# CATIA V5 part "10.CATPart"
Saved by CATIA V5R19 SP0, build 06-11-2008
Part number: 10
Bounding box of the stored display mesh (mm): x -125 to 125, y -74.978 to 485, z -260.425 to 324.922
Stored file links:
  G:\EU_thinkMotion\CFAO_2010\MMS_groupe3\MMS_groupe3\A reprendre\bblot\BLOT\10.CATPart
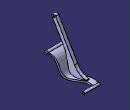
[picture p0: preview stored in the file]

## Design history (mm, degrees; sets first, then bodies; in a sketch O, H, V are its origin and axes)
Body1 (main body)
  DatumCurve1
  DatumCurve2
  Plane1 "Plan 9-10 droite": stored without definition
  Plane2 "Plan 9-10 gauche": stored without definition
  DatumSurface1
  Sketch1 on xy-plane, origin (0, 0, 0), H (1, 0, 0), V (0, 1, 0)
    point P1 (-125, 0)
    line L1 (-125, 0) -> (-125, 12.5)
    line L2 (-125, 12.5) -> (-100, 12.5)
    line L3 (-100, 12.5) -> (-100, 17)
    line L4 (-100, 17) -> (100, 17)
    line L5 (100, 17) -> (100, 12.5)
    point P6 (100, 12.5)
    line L6 (100, 12.5) -> (125, 12.5)
    line L7 (125, 12.5) -> (125, 0)
    point P8 (125, 0)
    line L8 (125, 0) -> (-125, 0)
    reference projected line E1 (-120, 40) -> (-120, -40) from edge of DatumCurve1
    reference projected line E2 (120, 40) -> (120, -160) from edge of DatumCurve2
    reference intersected line E3 through (-100, 0) direction (0, 1) from Plane1
    reference intersected line E4 through (100, 0) direction (0, 1) from Plane2
    axis line L9 (125, 0) -> (-125, 0)
    distance E1 L1 = 5
    distance L7 E2 = 5
    distance L2 L8 = 12.5
    distance L8 L4 = 17
    coincidence: P1 H, P6 L2, P8 H, L3 E3, L5 E4
    vertical: L1 V, L3 V, L5 V, L7 V
    horizontal: L2 H, L4 H, L6 H, L8 H, L9 H
  Shaft1: profile Sketch1, axis Sketch1.L9, angle 360
  DatumCurve3
  DatumSurface2
  Sketch2 on face of DatumSurface1, origin (-100, 0, 0), H (0, -1, 0), V (0, 0, 1)
    circle A1 centre (-470, -220) radius 10
    circle A2 centre (-470, -220) radius 15
    reference projected circle E1 centre (-470, -220) radius 10 from edge of DatumCurve3
    distance A1 A2 = 5
    coincidence: A1 E1
  Pad1: profile Sketch2, direction (-1, 0, 0), up to face of DatumSurface2
  Line1 "BE": stored without definition
  Line2 "as (BF)": stored without definition
  Plane3: type 2Lines, Element1 Line1, Element2 Line2
  Line3 "ab": stored without definition
  Plane4 "Plan 9-10 gauche": stored without definition
  Line4 "as (BF)": stored without definition
  DatumSurface3
  DatumSurface4
  Line5 "ab": stored without definition
  Plane5 "Plan 9-10 droite": stored without definition
  Plane6 "Fig.2": stored without definition
  Plane7 "Fig.2": stored without definition
  Sketch3 on Plane6, origin (0, 0, 0), H (0, 1, 0), V (0, 0, 1)
    construction line L1 (12.2365, 2.5533) -> (5.8774, -11.0321)
    point P1 (12.2365, 2.5533)
    point P2 (5.8774, -11.0321)
    reference projected point E1 (9.0569, -4.2394) from vertex [element of Sketch4 | element of Sketch4]
    reference projected circle E2 centre (0, 0) radius 12.5 from edge [face of Shaft1 from Sketch1.L7 | face of Shaft1 from Sketch1.L6]
    reference projected circle E3 centre (0, 0) radius 12.5 from edge [face of Shaft1 from Sketch1.L7 | face of Shaft1 from Sketch1.L6]
    arc A1 centre (0, 0) radius 12.5 from (5.8774, -11.0321) to (12.2365, 2.5533) ccw
    axis line L2 (462.9472, -206.7615) -> (455.3163, -223.0639)
    point P4 (462.9472, -206.7615)
    point P5 (455.3163, -223.0639)
    reference projected point E4 (459.1317, -214.9127) from vertex [element of Sketch4 | element of Sketch4]
    reference projected circle E5 centre (470, -220) radius 15 from edge [face of Pad1 from Sketch2.A2 | end face of Pad1]
    reference projected circle E6 centre (470, -220) radius 15 from edge [face of Pad1 from Sketch2.A2 | end face of Pad1]
    arc A2 centre (470, -220) radius 15 from (462.9472, -206.7615) to (455.3163, -223.0639) ccw
    point P7 (462.9472, -206.7615)
    reference projected circle E7 centre (470, -220) radius 15 from edge [face of Pad1 from Sketch2.A2 | end face of Pad1]
    spline S1 through (455.3163, -223.0639) (350, -230) (140, -240) (75, -45) (5.8774, -11.0321)
    spline S2 through (462.9472, -206.7615) (340, -210) (160, -220) (100, -43) (12.2365, 2.5533)
    reference projected line E8 through (0, 0) direction (1, 0) from Line11
    reference projected line E9 through (0, 0) direction (0, 1) from Line12
    reference projected line E10 through (0, 0) direction (0, 1) from Line13
    reference projected line E11 (0, 0) -> (470, 0) from Line14
    reference projected line E12 through (0, 0) direction (0, 1) from Line15
    reference projected line E13 through (0, 0) direction (1, 0) from Line16
    reference projected line E14 through (0, 0) direction (1, 0) from Line17
    reference projected line E15 through (0, 0) direction (0, 1) from Line18
    reference projected line E16 through (0, 0) direction (0, 1) from Line19
    reference projected line E17 through (0, 0) direction (1, 0) from Line20
    reference projected line E18 through (0, 0) direction (1, 0) from Line21
    reference projected line E19 through (0, 0) direction (0, 1) from Line22
    point P8 (455.3163, -223.0639)
    point P9 (5.8774, -11.0321)
    point P10 (12.2365, 2.5533)
    point P11 (462.9472, -206.7615)
    point P12 (100, -43)
    point P13 (75, -45)
    point P14 (140, -240)
    point P15 (160, -220)
    point P16 (340, -210)
    point P17 (350, -230)
    distance P12 E8 = 43
    distance E9 P12 = 100
    distance E10 P13 = 75
    distance P13 E11 = 45
    distance P14 E12 = 140
    distance E13 P14 = 240
    distance P15 E14 = 220
    distance P15 E15 = 160
    distance P16 E16 = 340
    distance P16 E17 = 210
    distance P17 E18 = 230
    distance P17 E19 = 350
    midpoint: L1 E1, L2 E4
    coincidence: P1 E2, P2 E3, P4 E5, P5 E6, P7 L2, P7 P4, A2 E7, P8 P5, P9 P2, P10 P1, P11 P4
  Sketch4 on Plane3, origin (0, 0, 0), H (-1, 0, 0), V (0, -0.9057, 0.4239)
    spline S1 through (-95, -10) (-70, -145) (20, -371.9412) (30, -506.9412)
    spline S2 through (95, -10) (80, -145) (110, -371.9412) (95, -506.9412)
    reference projected line E1 through (0, 0) direction (-1, 0) from Line3
    reference intersected line E2 through (-100, 0) direction (0, -1) from Plane4
    reference projected line E3 through (0, -518.9412) direction (-1, 0) from Line4
    reference intersected line E4 (100, -508.9412) -> (100, -507.8999) from face of DatumSurface3
    reference intersected line E5 (100, -508.9412) -> (100, -507.8999) from face of DatumSurface4
    line L1 (95, -10) -> (-95, -10)
    point P1 (95, -10)
    point P2 (-95, -10)
    reference intersected line E6 through (100, 0) direction (0, -1) from Plane5
    line L2 (30, -506.9412) -> (95, -506.9412)
    point P3 (30, -506.9412)
    point P4 (95, -506.9412)
    construction line L3 (110, -371.9412) -> (20, -371.9412)
    point P5 (20, -371.9412)
    point P6 (110, -371.9412)
    axis line L4 (-70, -145) -> (80, -145)
    point P7 (80, -145)
    point P8 (-70, -145)
    point P9 (-95, -10)
    point P10 (30, -506.9412)
    point P11 (95, -506.9412)
    point P12 (95, -10)
    point P13 (20, -371.9412)
    point P14 (110, -371.9412)
    point P15 (80, -145)
    point P16 (-70, -145)
    distance P9 E1 = 10
    distance E2 P9 = 5
    distance E3 P10 = 12
    distance E4 P10 = 70
    distance E5 P11 = 5
    distance E6 P12 = 5
    distance L4 L1 = 135
    length L4 = 150
    distance P1 P15 H = 15
    distance L2 L3 = 135
    length L3 = 90
    distance P13 P16 H = 90
    coincidence: P12 P1, P9 P2, P10 P3, P11 P4, P13 P5, P6 P14, P15 P7, P8 P16
    horizontal: L1 H, L2 H, L3 H, L4 H
  SolidCombine1: FirstComponentProfile Sketch3, FirstComponentDirection Sketch3, SecondComponentProfile Sketch4, SecondComponentDirection Sketch4
  Line6: stored without definition
  Line7: stored without definition
  Plane8 "Plan 9-11": stored without definition
  Line8: stored without definition
  Line9: stored without definition
  Line10 "D\"C\"": stored without definition
  Sketch5 on Plane7, origin (0, 0, 0), H (0, 1, 0), V (0, 0, 1)
    point P1 (117, -85.7552)
    line L1 (117, -85.7552) -> (96.5926, -9.5937)
    line L2 (86.5131, 14.679) -> (-71.6283, 287.4613)
    point P2 (-71.6283, 287.4613)
    line L3 (117, -85.7552) -> (117, -190.8275)
    point P3 (117, -190.8275)
    line L4 (117, -190.8275) -> (216.0854, -259.3258)
    point P4 (216.0854, -259.3258)
    line L5 (216.0854, -259.3258) -> (430, -212.4537)
    point P5 (430, -212.4537)
    line L6 (430, -212.4537) -> (360.2266, -203.0932)
    line L7 (213.7932, -105.1783) -> (-28.3717, 312.5387)
    arc A1 centre (-50, 300) radius 25 from (-28.3717, 312.5387) to (-71.6283, 287.4613) ccw
    point P7 (-50, 300)
    point P8 (-71.6283, 287.4613)
    arc A2 centre (0, -35.4756) radius 100 from (96.5926, -9.5937) to (86.5131, 14.679) ccw
    point P11 (0, -35.4756)
    reference projected curve E1 from edge [face of SolidCombine1 from Sketch3.S2 | face of SolidCombine1 from Sketch4.S1]
    reference projected curve E2 from edge [face of SolidCombine1 from Sketch4.S1 | face of SolidCombine1 from Sketch3.S1]
    reference projected curve E3 from edge [face of SolidCombine1 from Sketch4.S1 | face of SolidCombine1 from Sketch3.S1]
    reference projected curve E4 from edge [face of SolidCombine1 from Sketch3.S2 | face of SolidCombine1 from Sketch4.S1]
    reference projected line E5 through (0, 0) direction (0, 1) from Line6
    reference projected curve E6 from edge [face of SolidCombine1 from Sketch4.S1 | face of SolidCombine1 from Sketch3.S1]
    reference projected line E7 through (470, 0) direction (0, 1) from Line7
    reference intersected line E8 through (0, 30) direction (-1, 0) from Plane8
    reference projected line E9 through (0, 0) direction (0, 1) from Line8
    reference projected line E10 through (0, 0) direction (0, 1) from Line9
    arc A3 centre (386.8194, -4.8691) radius 200 from (360.2266, -203.0932) to (213.7932, -105.1783) cw
    radius A2 = 100
    distance L3 E5 = 117
    distance E7 P5 = 40
    radius A1 = 25
    distance E8 P7 = 270
    distance E9 P7 = 50
    angle L3 L1 = 15
    angle L6 L5 = 20
    radius A3 = 200
    coincidence: P8 L2, P8 P2, P1 E1, P3 E2, P4 E3, P11 E10
    tangency: A1 L7, A1 L2, A2 L1, A2 L2, L4 E4, L5 E6, A3 L6, A3 L7
    vertical: L3 V
    parallelism: L7 L2
  Sketch6 on Plane3, origin (0, 0, 0), H (-1, 0, 0), V (0, -0.9057, 0.4239)
    point P1 (39.4492, -479.5144)
    line L1 (39.4492, -479.5144) -> (79.4492, -479.5144)
    point P2 (79.4492, -479.5144)
    point P3 (79.4492, -479.5144)
    line L2 (79.4492, -479.5144) -> (79.4492, 216.7394)
    line L3 (79.4492, 216.7394) -> (39.4492, 216.7394)
    line L4 (39.4492, 216.7394) -> (39.4492, -479.5144)
    point P6 (39.4492, -479.5144)
    reference projected point E1 (0, -479.5144) from vertex [element of Sketch5 | element of Sketch5]
    reference projected curve E2 from edge [face of SolidCombine1 from Sketch3.S2 | face of SolidCombine1 from Sketch4.S2]
    axis line L5 (-53.443, 186.7394) -> (132.9344, 186.7394)
    reference projected point E3 (0, 186.7394) from vertex [element of Sketch5 | element of Sketch5]
    distance L5 L3 = 30
    length L3 = 40
    horizontal: L1 H, L3 H, L5 H
    vertical: L2 V, L4 V
    coincidence: E1 L1, P3 P2, P6 P1, L5 E3
    tangency: L2 E2
  SolidCombine2: FirstComponentProfile Sketch5, FirstComponentDirection Sketch5, SecondComponentProfile Sketch6, SecondComponentDirection Sketch6
  Sketch7 on face of SolidCombine2 from Sketch6.L4, origin (-39.4492, -51.0289, 306.6253), H (0, 1, 0), V (0, 0, 1)
    point P1 (1.0289, -6.6253)
    reference projected arc E1 centre (1.0289, -6.6253) radius 25 from (22.6572, 5.9134) to (-20.5993, -19.164) ccw from edge [face of SolidCombine2 from Sketch5.A1 | face of SolidCombine2 from Sketch6.L4]
    concentricity: P1 E1
  Hole1: placed by Sketch7, at (-39.4492, -50, 300) direction (-1, 0, 0), diameter 20, through (limit type 3)
  Line11 "D\"C\"": stored without definition
  Line12 "ar": stored without definition
  Line13 "ar": stored without definition
  Line14 "EF": stored without definition
  Line15 "ar": stored without definition
  Line16 "D\"C\"": stored without definition
  Line17 "D\"C\"": stored without definition
  Line18 "ar": stored without definition
  Line19 "ar": stored without definition
  Line20 "D\"C\"": stored without definition
  Line21 "D\"C\"": stored without definition
  Line22 "ar": stored without definition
